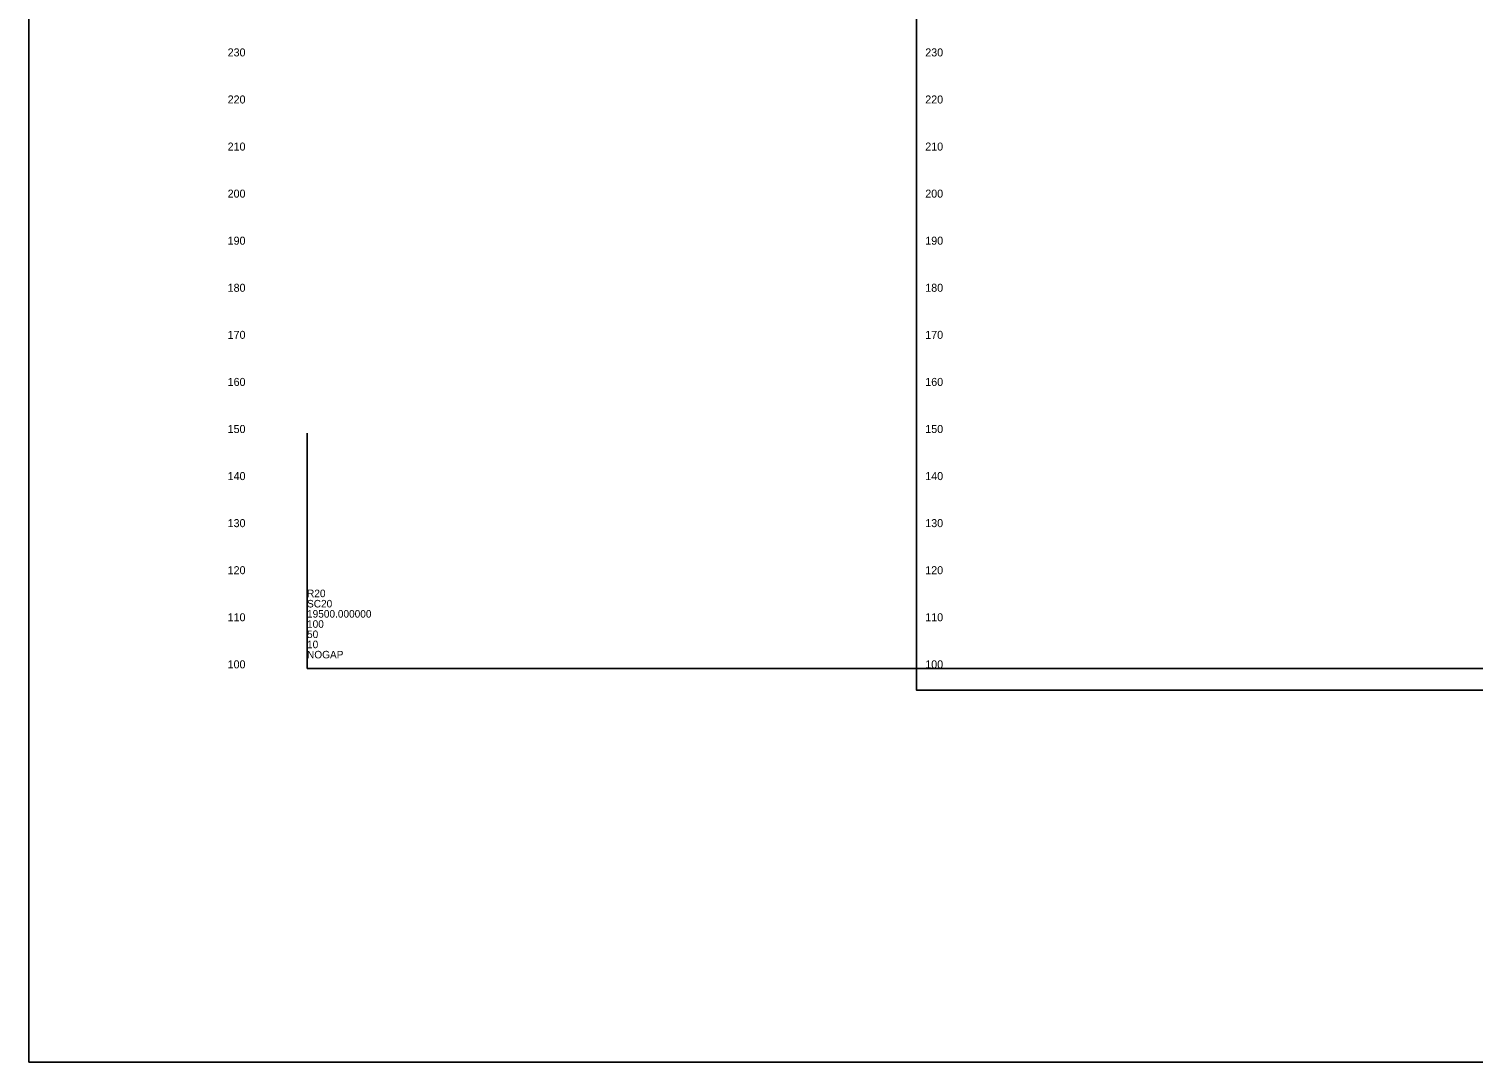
# Model space of a CAD drawing. Extents: x 2018315 to 2021915, y 966584 to 968784.
# Drawn here: x 2018315 to 2019848, y 966584 to 967682 of the extents above; entities that cross this region are included whole.
import ezdxf

# ---------------------------------------------------------------- set-up
doc = ezdxf.new("R2010")
doc.units = 0
for name, color, linetype in [('RD_DDB_ElevTX', 7, 'Continuous'), ('RD_GPK_Profile_Cell', 7, 'Continuous'), ('RD_SHT_IplotShp', 7, 'Continuous'), ('RD_SHT_ShtClip', 7, 'Continuous')]:
    doc.layers.add(name, color=color, linetype=linetype)

msp = doc.modelspace()

# ---------------------------------------------------------------- linework, layer by layer
at = {"layer": 'RD_GPK_Profile_Cell'}
for q in [(2018609.9, 967252.1), (2021709.9, 967002.1), (2018609.9, 967002.1)]:
    msp.add_line((2018609.9, 967002.1), q, dxfattribs=at)
at = {"layer": 'RD_SHT_IplotShp'}
msp.add_lwpolyline([(2018314.5, 966584.2), (2021914.5, 966584.2), (2021914.5, 968784.2), (2018314.5, 968784.2)], close=True, dxfattribs=at)
at = {"layer": 'RD_SHT_ShtClip'}
msp.add_lwpolyline([(2019257.2, 968079.2), (2021057.2, 968079.2), (2021057.2, 966979.2), (2019257.2, 966979.2)], close=True, dxfattribs=at)

# ---------------------------------------------------------------- texts
at = {"layer": 'RD_DDB_ElevTX'}
for s, p in [('230', (2018525.6, 967652.4)), ('230', (2019266.4, 967652.4)), ('220', (2018525.6, 967602.4)), ('220', (2019266.4, 967602.4)), ('210', (2018525.6, 967552.4)), ('210', (2019266.4, 967552.4)), ('200', (2018525.6, 967502.4)), ('200', (2019266.4, 967502.4)), ('190', (2018525.6, 967452.4)), ('190', (2019266.4, 967452.4)), ('180', (2018525.6, 967402.4)), ('180', (2019266.4, 967402.4)), ('170', (2018525.6, 967352.4)), ('170', (2019266.4, 967352.4)), ('160', (2018525.6, 967302.4)), ('160', (2019266.4, 967302.4)), ('150', (2018525.6, 967252.4)), ('150', (2019266.4, 967252.4)), ('140', (2018525.6, 967202.4)), ('140', (2019266.4, 967202.4)), ('130', (2018525.6, 967152.4)), ('130', (2019266.4, 967152.4)), ('120', (2018525.6, 967102.4)), ('120', (2019266.4, 967102.4)), ('110', (2018525.6, 967052.4)), ('110', (2019266.4, 967052.4)), ('100', (2018525.6, 967002.4)), ('100', (2019266.4, 967002.4))]:
    msp.add_text(s, height=8.5, dxfattribs=at).set_placement(p)
at = {"layer": 'RD_GPK_Profile_Cell'}
for s, p in [('R20', (2018609.9, 967078)), ('SC20', (2018609.9, 967067.1)), ('19500.000000', (2018609.9, 967056.3)), ('100', (2018609.9, 967045.5)), ('50', (2018609.9, 967034.6)), ('10', (2018609.9, 967023.8)), ('NOGAP', (2018609.9, 967013))]:
    msp.add_text(s, height=8, dxfattribs=at).set_placement(p)

doc.saveas('drawing.dxf')
